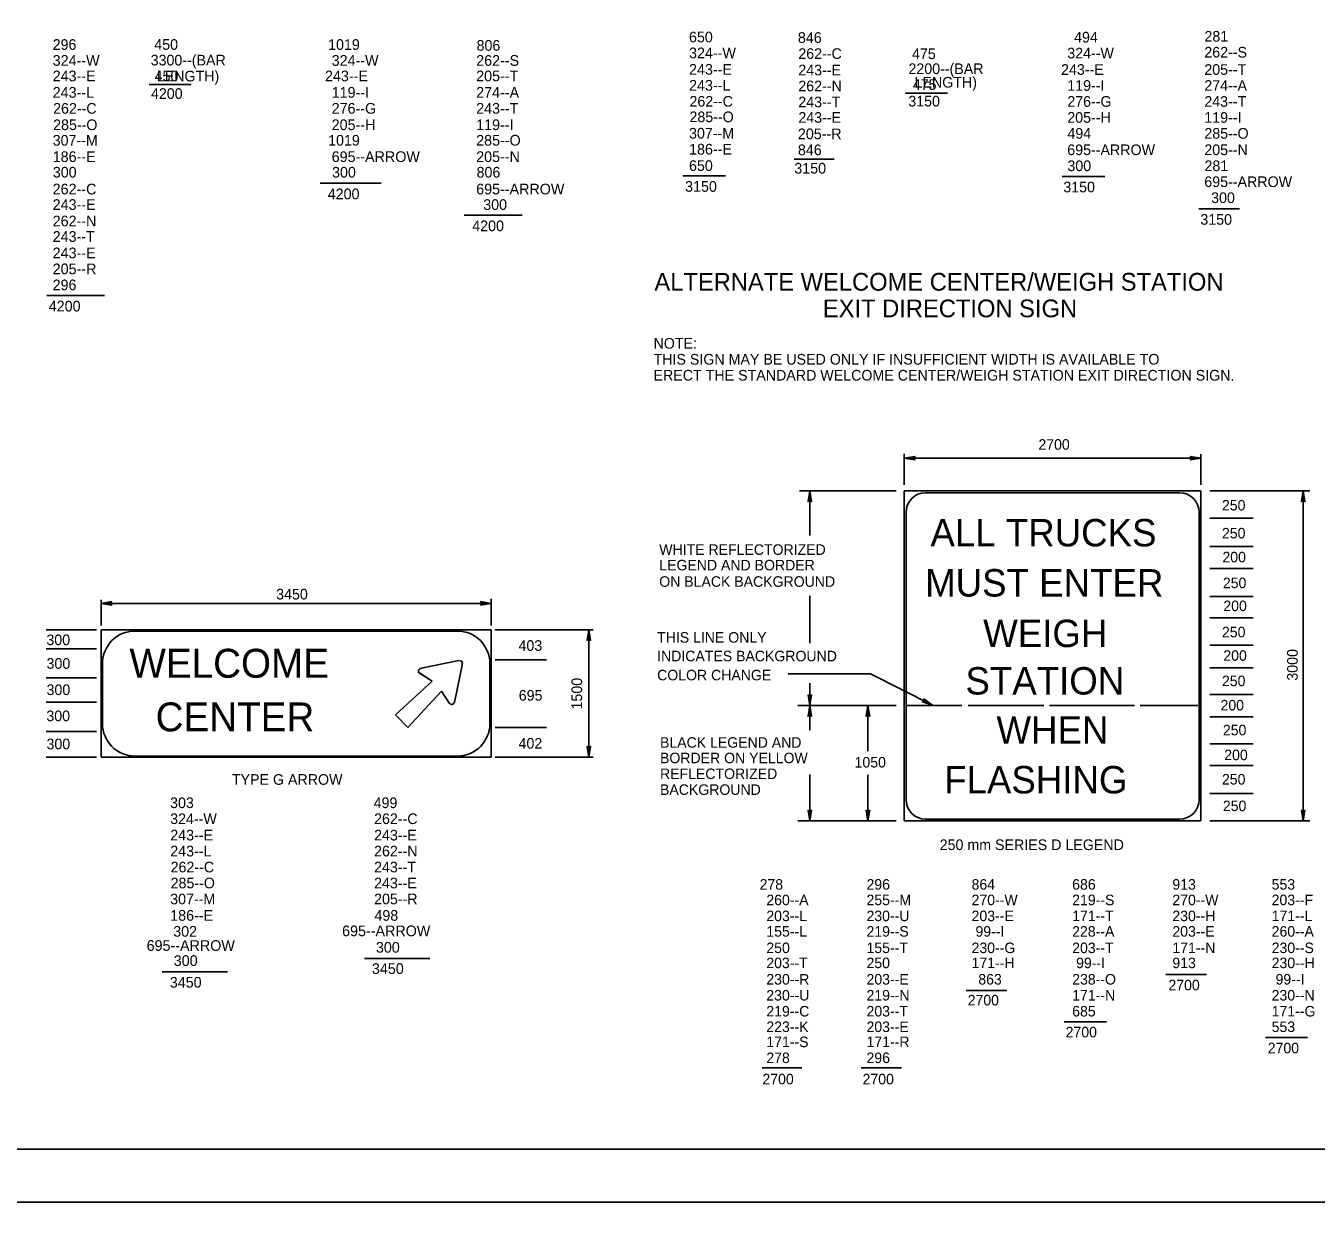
# Model space of a CAD drawing. Extents: x 638689 to 652291, y 298458 to 299646.
# Drawn here: x 651601.1 to 651965, y 299044.7 to 299383.4 of the extents above; entities that cross this region are included whole.
import ezdxf

# ---------------------------------------------------------------- set-up
doc = ezdxf.new("R2010")
doc.units = 0
for name, color, linetype in [('1', 7, 'Continuous'), ('2', 7, 'Continuous'), ('3', 7, 'Continuous'), ('PLT-BNDY', 7, 'Continuous')]:
    doc.layers.add(name, color=color, linetype=linetype)

# ---------------------------------------------------------------- blocks, each defined once
blk = doc.blocks.new('RARROW')
at = {"layer": '3'}
blk.add_lwpolyline([(-2.2695, 0.285), (-2.184875, 0.12075), (0, 0), (-2.2695, 0.285), (-2.38575, 0.384625), (0, 0), (-2.183125, -0.108), (-2.262875, -0.2705), (0, 0), (-2.38575, -0.379125), (-2.262875, -0.2705)], dxfattribs=at)

msp = doc.modelspace()

# ---------------------------------------------------------------- linework, layer by layer
at = {"layer": '1'}
for p, q in [((652212.31, 299066.75), (651426.31, 299066.75)), ((651426.31, 299066.75), (652012.31, 299066.75))]:
    msp.add_line(p, q, dxfattribs=at)
at = {"layer": '2'}
for p, q in [((651848.81, 299254), (651848.81, 299262.75)), ((651932.44, 299254), (651932.44, 299262.63)), ((651932.44, 299261.5), (651848.81, 299261.5)), ((651846.56, 299252.25), (651819.31, 299252.25)), ((651822.19, 299252.25), (651822.19, 299239.75)), ((651848.81, 299252.25), (651932.44, 299252.25)), ((651848.81, 299252.25), (651848.81, 299159.25)), ((651854.81, 299251.75), (651926.44, 299251.75)), ((651932.44, 299252.25), (651932.44, 299159.25)), ((651934.94, 299252.25), (651963.18, 299252.25)), ((651961.31, 299252.25), (651961.31, 299159.25)), ((651849.31, 299165.25), (651849.31, 299246.25)), ((651931.94, 299246.25), (651931.94, 299165.25)), ((651934.94, 299244.63), (651947.2, 299244.63)), ((651934.94, 299236.63), (651947.2, 299236.63)), ((651934.94, 299230.38), (651947.2, 299230.38)), ((651732.31, 299214.37), (651732.31, 299221.83)), ((651822.19, 299222.68), (651822.19, 299209.38)), ((651934.94, 299222.5), (651947.2, 299222.5)), ((651622.31, 299214.37), (651622.31, 299221.58)), ((651622.31, 299220.58), (651732.31, 299220.58)), ((651934.94, 299216.5), (651947.2, 299216.5)), ((651621.06, 299213.12), (651606.87, 299213.12)), ((651622.31, 299213.12), (651732.31, 299213.12)), ((651622.31, 299213.12), (651622.31, 299177.25)), ((651722.81, 299212.75), (651631.94, 299212.75)), ((651732.31, 299177.25), (651732.31, 299213.12)), ((651733.44, 299213.12), (651742.06, 299213.12)), ((651733.44, 299213.12), (651761.11, 299213.12)), ((651759.86, 299177.25), (651759.86, 299213.12)), ((651621.06, 299207.75), (651606.87, 299207.75)), ((651934.94, 299208.75), (651947.2, 299208.75)), ((651622.69, 299203.62), (651622.69, 299186.62)), ((651712.19, 299202.25), (651723.19, 299204.5)), ((651712.19, 299202.25), (651723.19, 299204.5)), ((651724.19, 299203.62), (651721.94, 299192.62)), ((651724.19, 299203.62), (651721.94, 299192.62)), ((651731.94, 299186.62), (651731.94, 299203.62)), ((651733.44, 299204.62), (651747.89, 299204.62)), ((651715.69, 299198.62), (651712.06, 299201)), ((651715.69, 299198.62), (651712.06, 299200.87)), ((651839.31, 299200.75), (651816.08, 299200.75)), ((651856.81, 299191.88), (651839.31, 299200.75)), ((651934.94, 299202.38), (651947.2, 299202.38)), ((651621.06, 299199.62), (651606.87, 299199.62)), ((651705.31, 299189.12), (651715.69, 299198.62)), ((651705.31, 299189.12), (651715.69, 299198.62)), ((651822.19, 299198.1), (651822.19, 299191.75)), ((651621.06, 299192.75), (651606.87, 299192.75)), ((651718.31, 299195.87), (651708.81, 299185.62)), ((651718.31, 299195.87), (651708.81, 299185.62)), ((651720.56, 299192.37), (651718.31, 299195.87)), ((651720.56, 299192.37), (651718.31, 299195.87)), ((651934.94, 299194.88), (651947.2, 299194.88)), ((651708.81, 299185.62), (651705.31, 299189.12)), ((651708.81, 299185.62), (651705.31, 299189.12)), ((651846.56, 299191.75), (651818.75, 299191.75)), ((651822.19, 299191.75), (651822.19, 299184.88)), ((651838.56, 299191.75), (651838.56, 299178.87)), ((651865.06, 299191.75), (651849.56, 299191.75)), ((651888.19, 299191.75), (651866.81, 299191.75)), ((651913.69, 299191.75), (651889.81, 299191.75)), ((651931.56, 299191.75), (651915.31, 299191.75)), ((651733.44, 299185.62), (651747.89, 299185.62)), ((651934.94, 299188.63), (651947.2, 299188.63)), ((651621.06, 299184.5), (651606.87, 299184.5)), ((651934.94, 299181), (651947.2, 299181)), ((651621.06, 299177.25), (651606.87, 299177.25)), ((651732.31, 299177.25), (651622.31, 299177.25)), ((651631.94, 299177.5), (651722.81, 299177.5)), ((651733.44, 299177.25), (651761.11, 299177.25)), ((651934.94, 299174.88), (651947.2, 299174.88)), ((651822.19, 299172.38), (651822.19, 299159.25)), ((651838.56, 299172.25), (651838.56, 299159.25)), ((651934.94, 299167), (651947.2, 299167)), ((651846.56, 299159.25), (651818.75, 299159.25)), ((651848.81, 299159.25), (651932.44, 299159.25)), ((651926.44, 299159.75), (651854.81, 299159.75)), ((651934.94, 299159.25), (651963.18, 299159.25))]:
    msp.add_line(p, q, dxfattribs=at)
for centre, radius, start, end in [((651854.81, 299246.25), 5.5, 90, 180), ((651926.44, 299246.25), 5.5, 0, 90), ((651631.85, 299203.63), 9.14, 90, 180), ((651722.8, 299203.63), 9.14, 0, 90), ((651723.49, 299203.76), 0.686, 348.2602, 101.7398), ((651723.49, 299203.76), 0.686, 348.2602, 101.7398), ((651712.47, 299201.47), 0.686, 101.7398, 236.6838), ((651712.47, 299201.47), 0.686, 101.7398, 236.6838), ((651721.2, 299192.75), 0.686, 213.3162, 348.2602), ((651721.2, 299192.75), 0.686, 213.3162, 348.2602), ((651631.85, 299186.66), 9.14, 180, 270), ((651722.8, 299186.66), 9.14, 270, 0), ((651854.81, 299165.25), 5.5, 180, 270), ((651926.44, 299165.25), 5.5, 270, 0)]:
    msp.add_arc(centre, radius, start, end, dxfattribs=at)
at = {"layer": '3'}
for p, q in [((651635.84, 299366.85), (651647.67, 299366.85)), ((651849.16, 299364.41), (651861.03, 299364.41)), ((651817.76, 299345.82), (651829.02, 299345.82)), ((651684.09, 299338.98), (651701.34, 299338.98)), ((651786.33, 299341.09), (651798.38, 299341.09)), ((651893.32, 299340.92), (651905.37, 299340.92)), ((651931.83, 299331.8), (651943.35, 299331.8)), ((651724.72, 299329.98), (651741.09, 299329.98)), ((651607.05, 299307.35), (651623.3, 299307.35)), ((651696.56, 299120.5), (651715.06, 299120.5)), ((651639.56, 299116.75), (651657.94, 299116.75)), ((651922.56, 299116), (651934.06, 299116)), ((651866.31, 299111.5), (651877.69, 299111.5)), ((651893.94, 299102.63), (651905.81, 299102.63)), ((651950.69, 299098.25), (651962.56, 299098.25)), ((651808.69, 299089.63), (651819.94, 299089.63)), ((651836.69, 299089.63), (651848.06, 299089.63))]:
    msp.add_line(p, q, dxfattribs=at)
at = {"layer": 'PLT-BNDY'}
for points in [[(651386.31, 299645.75), (652227.31, 299645.75), (652227.31, 299051.75), (651386.31, 299051.75)], [(651386.31, 299051.75), (652227.31, 299051.75), (652227.31, 298457.75), (651386.31, 298457.75)]]:
    msp.add_lwpolyline(points, close=True, dxfattribs=at)

# ---------------------------------------------------------------- block references
at = {"layer": '2'}
for p, xscale, yscale, rotation in [((651848.81, 299261.5), 1.2574347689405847, 1.3092961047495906, 180), ((651822.19, 299252.25), 1.2574347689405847, 1.3092961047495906, 89.99999999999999), ((651961.31, 299252.25), 1.2574347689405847, 1.3092961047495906, 89.99999999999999), ((651622.31, 299220.58), 1.2574347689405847, 1.3092961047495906, 180), ((651759.86, 299213.12), 1.2574347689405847, 1.3092961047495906, 89.99999999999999), ((651822.19, 299191.75), 1.2574347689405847, 1.3092961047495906, -90.00000000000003), ((651856.81, 299191.88), 1.2574347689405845, 1.3092961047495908, -26.733042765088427), ((651822.19, 299191.75), 1.2574347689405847, 1.3092961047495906, 89.99999999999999), ((651838.56, 299191.75), 1.2574347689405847, 1.3092961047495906, 89.99999999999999), ((651759.86, 299177.25), 1.2574347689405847, 1.3092961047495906, -90.00000000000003), ((651822.19, 299159.25), 1.2574347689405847, 1.3092961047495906, -90.00000000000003), ((651838.56, 299159.25), 1.2574347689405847, 1.3092961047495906, -90.00000000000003), ((651961.31, 299159.25), 1.2574347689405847, 1.3092961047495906, -90.00000000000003)]:
    msp.add_blockref('RARROW', p, dxfattribs=dict(at, xscale=xscale, yscale=yscale, rotation=rotation))
at = {"layer": '2', "xscale": 1.2574347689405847, "yscale": 1.3092961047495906}
for p in [(651932.44, 299261.5), (651732.31, 299220.58)]:
    msp.add_blockref('RARROW', p, dxfattribs=at)

# ---------------------------------------------------------------- texts
at = {"layer": '2'}
for s, height, p in [(' 281       ', 3, (651932.35, 299378.92)), (' 296   ', 3, (651607.55, 299376.6)), (' 450               ', 3, (651636.21, 299376.61)), ('1019       ', 3, (651686.34, 299376.6)), (' 806       ', 3, (651727.09, 299376.35)), (' 650   ', 3, (651787, 299378.72)), (' 846   ', 3.016, (651817.69, 299378.54)), ('494      ', 3, (651896.7, 299378.67)), (' 324--W', 3.016, (651607.55, 299372.1)), ('3300--(BAR', 3, (651636.3, 299372.2)), (' 324--W    ', 3.0158, (651686.22, 299372.1)), (' 262--S    ', 3.0158, (651726.97, 299372.1)), (' 324--W', 3.016, (651787, 299374.22)), (' 262--C', 3, (651817.82, 299374.04)), (' 475               ', 3, (651849.88, 299373.99)), (' 324--W    ', 3, (651893.66, 299374.18)), (' 262--S    ', 3, (651932.31, 299374.43)), (' 243--E', 3.016, (651787, 299369.59)), (' 243--E', 3, (651817.82, 299369.41)), ('2200--(BAR', 3, (651849.99, 299369.78)), ('  243--E     ', 3, (651890.8, 299369.55)), (' 205--T    ', 3, (651932.31, 299369.55)), (' 243--E', 3.016, (651607.55, 299367.73)), (' 450               ', 3, (651636.3, 299367.73)), ('         LENGTH)', 3, (651628, 299367.7)), ('  243--E     ', 3.0158, (651683.22, 299367.73)), (' 205--T    ', 3.0158, (651726.97, 299367.73)), (' 243--L', 3.016, (651787, 299365.09)), (' 262--N', 3, (651817.82, 299364.91)), (' 475               ', 3, (651850.09, 299365.32)), ('         LENGTH)', 3, (651841.68, 299365.96)), (' 119--I    ', 3, (651893.66, 299365.05)), (' 274--A    ', 3, (651932.31, 299365.05)), (' 243--L', 3.016, (651607.55, 299363.1)), ('4200              ', 3, (651636.38, 299362.77)), (' 119--I    ', 3.0158, (651686.22, 299363.1)), (' 274--A    ', 3.0158, (651726.97, 299363.1)), ('3150             ', 3, (651849.95, 299360.64)), (' 262--C', 3, (651607.68, 299358.6)), (' 276--G    ', 3.0158, (651686.22, 299358.6)), (' 243--T    ', 3.0158, (651726.97, 299358.6)), (' 262--C', 3, (651787.12, 299360.59)), (' 243--T', 3, (651817.82, 299360.41)), (' 276--G    ', 3, (651893.66, 299360.55)), (' 243--T    ', 3, (651932.31, 299360.55)), (' 285--O', 3, (651607.68, 299353.98)), (' 205--H    ', 3.0158, (651686.22, 299353.98)), (' 119--I    ', 3.0158, (651726.97, 299353.98)), (' 285--O', 3, (651787.12, 299356.22)), (' 243--E', 3, (651817.82, 299356.04)), (' 205--H    ', 3, (651893.66, 299356.05)), (' 119--I    ', 3, (651932.31, 299356.05)), (' 307--M', 3, (651787, 299351.59)), (' 205--R', 3.016, (651817.69, 299351.41)), (' 494       ', 3, (651893.7, 299351.55)), (' 285--O    ', 3, (651932.31, 299351.55)), (' 307--M', 3, (651607.55, 299349.6)), ('1019       ', 3, (651686.34, 299349.6)), (' 285--O    ', 3.0158, (651726.97, 299349.6)), (' 186--E', 3.016, (651787, 299347.09)), (' 846   ', 3.016, (651817.69, 299346.91)), (' 695--ARROW', 3, (651893.66, 299346.93)), (' 205--N    ', 3, (651932.31, 299346.93)), (' 186--E', 3.016, (651607.55, 299344.98)), (' 695--ARROW', 3.0158, (651686.22, 299344.98)), (' 205--N    ', 3.0158, (651726.97, 299344.98)), (' 650   ', 3, (651787, 299342.47)), (' 300       ', 3, (651893.7, 299342.42)), (' 281       ', 3, (651932.35, 299342.42)), (' 300   ', 3, (651607.6, 299340.61)), (' 300       ', 3, (651686.34, 299340.6)), (' 806       ', 3, (651727.09, 299340.6)), ('3150   ', 3.016, (651817.79, 299341.72)), (' 262--C', 3.016, (651607.55, 299335.85)), (' 695--ARROW', 3.0158, (651726.97, 299335.85)), ('3150   ', 3.016, (651787, 299336.59)), ('3150       ', 3, (651893.66, 299336.43)), (' 695--ARROW', 3, (651932.31, 299337.93)), ('4200       ', 3.0158, (651686.22, 299334.48)), ('300      ', 3, (651935.35, 299333.42)), (' 243--E', 3.016, (651607.55, 299331.48)), ('300      ', 3, (651730.09, 299331.48)), (' 262--N', 3.016, (651607.55, 299326.85)), ('4200       ', 3.0158, (651726.97, 299325.48)), ('3150       ', 3, (651932.31, 299327.3)), (' 243--T', 3.016, (651607.55, 299322.48)), (' 243--E', 3.016, (651607.55, 299317.85)), (' 205--R', 3.016, (651607.55, 299313.35)), ('ALTERNATE WELCOME CENTER/WEIGH STATION', 5, (651778.35, 299308.72)), (' 296   ', 3, (651607.55, 299308.85)), ('4200   ', 3.016, (651607.55, 299302.85)), ('EXIT DIRECTION SIGN', 5, (651825.85, 299301.22)), ('NOTE:', 3, (651778.1, 299292.38)), ('THIS SIGN MAY BE USED ONLY IF INSUFFICIENT WIDTH IS AVAILABLE TO ', 3, (651778.1, 299287.88)), ('ERECT THE STANDARD WELCOME CENTER/WEIGH STATION EXIT DIRECTION SIGN.', 3, (651778.1, 299283.38)), ('2700', 2.966, (651886.64, 299263.89)), ('250', 2.966, (651938.4, 299246.76)), ('ALL TRUCKS', 7.728, (651856.19, 299236.63)), ('250', 2.966, (651938.4, 299238.88)), ('WHITE REFLECTORIZED', 2.9663, (651779.72, 299234.25)), ('LEGEND AND BORDER', 2.9663, (651779.72, 299229.88)), ('200', 2.966, (651938.53, 299232.14)), ('MUST ENTER', 7.728, (651854.69, 299222.5)), ('ON BLACK BACKGROUND', 2.9663, (651779.72, 299225.25)), ('250', 2.966, (651938.66, 299224.86)), ('3450', 3, (651671.69, 299221.67)), ('200', 2.966, (651938.79, 299218.39)), ('WEIGH', 7.728, (651871.06, 299208.25)), ('300', 3, (651606.89, 299208.8)), ('THIS LINE ONLY', 2.9663, (651779.12, 299209.5)), ('250', 2.966, (651938.4, 299211)), ('WELCOME', 8.143, (651630.31, 299199.62)), ('403', 3, (651740.03, 299207.19)), ('INDICATES BACKGROUND', 2.9663, (651779.12, 299204.25)), ('200', 2.966, (651938.79, 299204.39)), ('300', 3, (651606.93, 299202.14)), ('COLOR CHANGE', 2.9663, (651779.12, 299198.88)), ('STATION', 7.728, (651866.06, 299194.88)), ('250', 2.966, (651938.4, 299197.24)), ('300', 3, (651606.93, 299194.73)), ('CENTER', 8.143, (651637.69, 299184.5)), ('695', 3, (651740.09, 299193.15)), ('200', 2.966, (651938, 299190.39)), ('300', 3, (651606.88, 299187.37)), ('WHEN', 7.728, (651874.81, 299181)), ('250', 2.966, (651938.66, 299183.38)), ('300', 3, (651606.92, 299179.44)), ('402', 3, (651740.04, 299179.63)), ('BLACK LEGEND AND', 2.9663, (651779.93, 299179.89)), ('BORDER ON YELLOW', 2.9663, (651779.93, 299175.52)), ('200', 2.966, (651939.05, 299176.38)), ('1050', 2.966, (651834.81, 299174.31)), ('FLASHING', 7.728, (651860.06, 299167)), ('TYPE G ARROW', 3, (651659.19, 299169.44)), ('REFLECTORIZED ', 2.9663, (651779.93, 299171.06)), ('250', 2.966, (651938.4, 299169.51)), ('BACKGROUND', 2.966, (651779.93, 299166.59)), (' 303 ', 3, (651640.66, 299162.87)), (' 499   ', 3, (651698.06, 299162.87)), ('250', 2.966, (651938.66, 299162.01)), (' 324--W', 3, (651640.69, 299158.37)), (' 262--C', 3, (651698.19, 299158.37)), (' 243--E', 3.016, (651640.69, 299153.75)), (' 243--E', 3, (651698.19, 299153.75)), ('250 mm SERIES D LEGEND', 3, (651858.8, 299151.04)), (' 243--L', 3.016, (651640.69, 299149.25)), (' 262--N', 3, (651698.19, 299149.25)), (' 262--C', 3, (651640.81, 299144.75)), (' 243--T', 3, (651698.19, 299144.75)), (' 285--O', 3, (651640.81, 299140.25)), (' 243--E', 3, (651698.19, 299140.25)), ('  278    ', 2.966, (651805.81, 299139.88)), (' 296   ', 2.966, (651837.06, 299139.88)), (' 864   ', 2.966, (651866.69, 299139.88)), (' 686   ', 2.966, (651895.06, 299139.88)), (' 913   ', 2.966, (651923.31, 299139.88)), (' 553   ', 2.966, (651951.31, 299139.88)), (' 307--M', 3, (651640.69, 299135.75)), (' 205--R', 3, (651698.19, 299135.75)), (' 260--A', 2.966, (651808.81, 299135.5)), (' 255--M', 2.966, (651837.06, 299135.5)), (' 270--W', 2.966, (651866.69, 299135.5)), (' 219--S', 2.966, (651895.06, 299135.5)), (' 270--W', 2.966, (651923.31, 299135.5)), (' 203--F', 2.966, (651951.31, 299135.5)), (' 186--E', 3.016, (651640.69, 299131.12)), (' 498  ', 3, (651698.29, 299131.12)), (' 203--L', 2.966, (651808.81, 299131)), (' 230--U', 2.966, (651837.06, 299131)), (' 203--E', 2.966, (651866.69, 299131)), (' 171--T', 2.966, (651895.06, 299131)), (' 230--H', 2.966, (651923.31, 299131)), (' 171--L', 2.966, (651951.31, 299131)), (' 302  ', 3, (651641.56, 299126.62)), ('      695--ARROW', 3.0158, (651683.56, 299126.75)), (' 155--L', 2.966, (651808.81, 299126.63)), (' 219--S', 2.966, (651837.06, 299126.63)), ('  99--I', 2.966, (651866.69, 299126.63)), (' 228--A', 2.966, (651895.06, 299126.63)), (' 203--E', 2.966, (651923.31, 299126.63)), (' 260--A', 2.966, (651951.31, 299126.63)), ('     695--ARROW', 3.0158, (651629.56, 299122.62)), (' 300   ', 3.016, (651698.69, 299122.12)), (' 250   ', 2.966, (651808.81, 299122)), (' 155--T', 2.966, (651837.06, 299122)), (' 230--G', 2.966, (651866.69, 299122)), (' 203--T', 2.966, (651895.06, 299122)), (' 171--N', 2.966, (651923.31, 299122)), (' 230--S', 2.966, (651951.31, 299122)), (' 300   ', 3.016, (651641.69, 299118.37)), (' 203--T', 2.966, (651808.81, 299117.75)), (' 250   ', 2.966, (651837.06, 299117.75)), (' 171--H', 2.966, (651866.69, 299117.75)), ('  99--I', 2.966, (651895.06, 299117.75)), (' 913   ', 2.966, (651923.31, 299117.75)), (' 230--H', 2.966, (651951.31, 299117.75)), ('3450   ', 3.016, (651698.69, 299116.12)), ('3450   ', 3.016, (651641.69, 299112.25)), (' 230--R', 2.966, (651808.81, 299113.13)), (' 203--E', 2.966, (651837.06, 299113.13)), ('863   ', 2.966, (651869.69, 299113.13)), (' 238--O', 2.966, (651895.06, 299113.13)), ('2700   ', 2.966, (651923.31, 299111.5)), ('  99--I', 2.966, (651951.31, 299113.13)), (' 230--U', 2.966, (651808.81, 299108.63)), (' 219--N', 2.966, (651837.06, 299108.63)), ('2700   ', 2.966, (651866.69, 299107.25)), (' 171--N', 2.966, (651895.06, 299108.63)), (' 230--N', 2.966, (651951.31, 299108.63)), (' 219--C', 2.966, (651808.81, 299104.13)), (' 203--T', 2.966, (651837.06, 299104.13)), (' 685   ', 2.966, (651895.06, 299104.13)), (' 171--G', 2.966, (651951.31, 299104.13)), (' 223--K', 2.966, (651808.81, 299099.75)), (' 203--E', 2.966, (651837.06, 299099.75)), (' 553   ', 2.966, (651951.31, 299099.75)), (' 171--S', 2.966, (651808.81, 299095.5)), (' 171--R', 2.966, (651837.06, 299095.5)), ('2700 ', 2.966, (651894.31, 299098.25)), ('2700   ', 2.966, (651951.31, 299093.75)), (' 278   ', 2.966, (651808.81, 299091)), (' 296   ', 2.966, (651837.06, 299091)), ('2700   ', 2.966, (651808.81, 299085)), ('2700   ', 2.966, (651837.06, 299085))]:
    msp.add_text(s, height=height, dxfattribs=at).set_placement(p)
for s, p in [('3000', (651959.76, 299198.78)), ('1500', (651757.96, 299190.66))]:
    msp.add_text(s, height=3, rotation=90, dxfattribs=at).set_placement(p)

doc.saveas('drawing.dxf')
